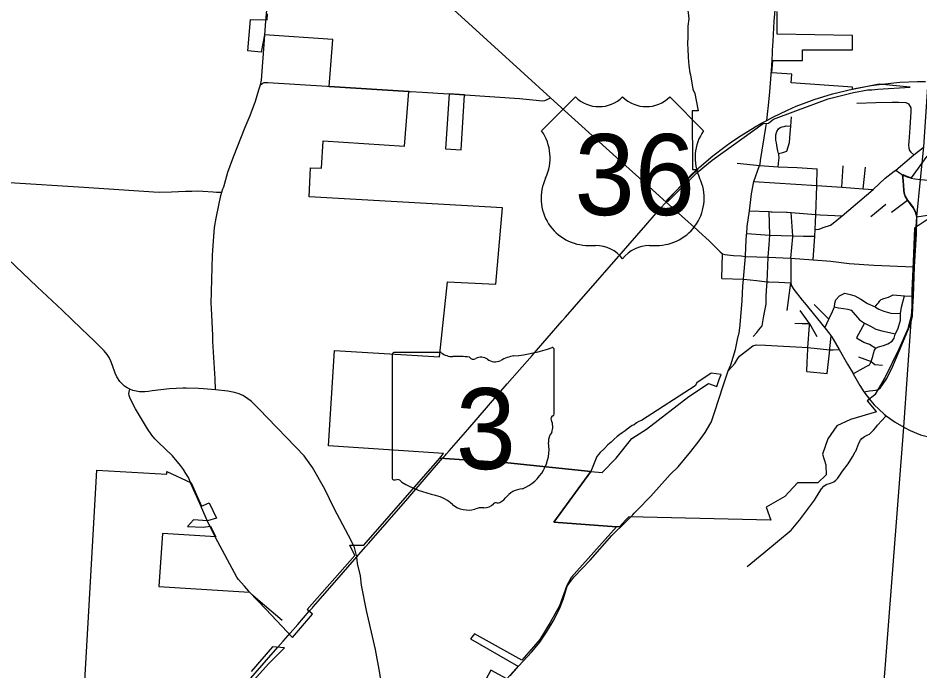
# Model space of a CAD drawing. Extents: x 1729596 to 1925846, y 659247 to 911751.
# Drawn here: x 1855559 to 1871056, y 810051 to 821273 of the extents above; entities that cross this region are included whole.
import ezdxf

# ---------------------------------------------------------------- set-up
doc = ezdxf.new("R2010")
doc.units = 0
for name, color, linetype in [('GM_X_City_Street', 7, 'Continuous'), ('GM_X_Corporation', 7, 'Continuous'), ('GM_X_County_Road', 7, 'Continuous'), ('GM_X_State_Route', 7, 'Continuous'), ('GM_X_State_Shield', 7, 'Continuous'), ('GM_X_Township', 7, 'Continuous'), ('GM_X_Township_Road', 7, 'Continuous'), ('GM_X_US_Route', 7, 'Continuous'), ('GM_X_US_Shield', 7, 'Continuous')]:
    doc.layers.add(name, color=color, linetype=linetype)

msp = doc.modelspace()

# ---------------------------------------------------------------- linework, layer by layer
at = {"layer": 'GM_X_City_Street'}
for points in [[(1859794, 820906), (1859818, 821219)], [(1862296, 820012), (1862506, 819999)], [(1862770, 819982), (1862964, 819970), (1862980, 819969)], [(1863244, 819953), (1864174, 819889), (1864402, 819867), (1864570, 819853), (1864610, 819857), (1864649, 819871), (1864708, 819903)], [(1869969, 819812), (1870296, 819821), (1870580, 819825), (1870662, 819825)], [(1870662, 819825), (1870665, 819825), (1870686, 819825), (1870812, 819821), (1870858, 819797), (1870899, 819732), (1870898, 819669), (1870883, 819386), (1870863, 819146), (1870862, 819092), (1870864, 819034), (1870877, 818999), (1870902, 818968), (1870950, 818924)], [(1868627, 818944), (1868702, 818965), (1868767, 818983), (1868813, 819135), (1868824, 819291), (1868837, 819417), (1868848, 819578)], [(1868318, 818823), (1868408, 819390), (1868417, 819463)], [(1868619, 818717), (1868634, 818829), (1868636, 818865), (1868630, 818931), (1868627, 818944), (1868616, 818991), (1868603, 819050), (1868589, 819130), (1868581, 819174), (1868580, 819266), (1868596, 819326), (1868624, 819370), (1868657, 819390), (1868687, 819404), (1868723, 819412), (1868755, 819418), (1868837, 819417)], [(1870615, 818642), (1870639, 818661), (1870950, 818924), (1871110, 819046)], [(1867916, 818779), (1868190, 818751), (1868191, 818751)], [(1868078, 817555), (1868079, 817572), (1868088, 817688), (1868126, 817958), (1868161, 818253), (1868200, 818465), (1868301, 818741), (1868308, 818760), (1868318, 818823)], [(1868191, 818751), (1868250, 818745), (1868301, 818741), (1868619, 818717), (1868949, 818705), (1869292, 818679)], [(1868836, 817146), (1869223, 817120), (1869252, 817526), (1869257, 817637), (1869326, 817645), (1869394, 817673), (1869522, 817716), (1869565, 817745), (1869717, 817873), (1870254, 818326), (1870457, 818519), (1870615, 818642)], [(1869257, 817637), (1869264, 817763), (1869268, 817897), (1869284, 818388), (1869285, 818397), (1869292, 818679)], [(1869714, 818365), (1869739, 818731)], [(1870083, 818338), (1870123, 818713)], [(1870639, 818661), (1870705, 818615), (1870759, 818578), (1870769, 818573)], [(1868200, 818465), (1869285, 818397), (1869714, 818365), (1870083, 818338), (1870254, 818326)], [(1870569, 817936), (1870841, 818142)], [(1870211, 817860), (1870470, 818075)], [(1868126, 817958), (1868463, 817946), (1868499, 817944), (1868515, 817944)], [(1868465, 817382), (1868477, 817541), (1868463, 817946)], [(1868515, 817944), (1868765, 817935), (1868777, 817934)], [(1868777, 817934), (1868845, 817932), (1869268, 817897), (1869342, 817891), (1869717, 817873)], [(1868870, 817512), (1868872, 817530), (1868845, 817932)], [(1870997, 817576), (1871001, 817788)], [(1868056, 817177), (1868065, 817339), (1868078, 817555)], [(1868079, 817572), (1868477, 817541)], [(1868477, 817541), (1868865, 817530)], [(1868836, 817146), (1868870, 817512)], [(1868865, 817530), (1868872, 817530), (1869053, 817525), (1869252, 817526)], [(1868441, 817012), (1868448, 817163), (1868465, 817382)], [(1867651, 816799), (1867664, 817220)], [(1868026, 816789), (1868056, 817177)], [(1869223, 817120), (1869523, 817094), (1869840, 817054), (1870261, 817024), (1870943, 816996), (1870961, 816995)], [(1868420, 816588), (1868429, 816742), (1868441, 817012)], [(1867651, 816799), (1868026, 816783), (1868029, 816783)], [(1867945, 815848), (1867947, 815858), (1867966, 816000), (1868000, 816416), (1868012, 816665), (1868026, 816783), (1868026, 816789)], [(1868029, 816783), (1868245, 816761), (1868429, 816742), (1868459, 816741)], [(1868459, 816741), (1868634, 816731), (1868837, 816721)], [(1868776, 816244), (1868837, 816721)], [(1868193, 815800), (1868251, 815868), (1868290, 815913), (1868344, 815981), (1868375, 816154), (1868411, 816354), (1868414, 816482), (1868420, 816588)], [(1869420, 815948), (1869492, 816098), (1869556, 816230), (1869590, 816308), (1869593, 816374), (1869609, 816429), (1869672, 816496), (1869765, 816547)], [(1869765, 816547), (1869857, 816521), (1869939, 816498), (1870039, 816440), (1870157, 816365), (1870285, 816308), (1870295, 816304), (1870349, 816267), (1870437, 816233), (1870557, 816202), (1870723, 816195)], [(1869910, 815156), (1870029, 815227), (1870080, 815254), (1870132, 815283), (1870188, 815314), (1870220, 815371), (1870244, 815454), (1870259, 815510), (1870275, 815562), (1870297, 815598), (1870343, 815622), (1870428, 815646), (1870502, 815675), (1870578, 815717), (1870611, 815773), (1870633, 815841), (1870636, 815847), (1870680, 815941), (1870721, 816079), (1870723, 816195), (1870740, 816306), (1870790, 816499)], [(1870285, 816308), (1870321, 816354), (1870345, 816378), (1870368, 816410), (1870392, 816438), (1870436, 816453), (1870516, 816477), (1870596, 816514), (1870790, 816499), (1870933, 816495), (1870947, 816494)], [(1869492, 816098), (1869239, 816348)], [(1869590, 816308), (1869656, 816290), (1869745, 816281), (1869819, 816271), (1869874, 816255), (1870015, 816089), (1870104, 816030), (1870115, 816022), (1870205, 815976), (1870301, 815925), (1870403, 815896), (1870636, 815847)], [(1869157, 816021), (1869157, 816024), (1868996, 816244)], [(1868907, 816028), (1869031, 816023), (1869157, 816024), (1869282, 815797)], [(1869128, 815581), (1869129, 815613), (1869160, 815986), (1869157, 816021)], [(1870104, 816030), (1869966, 815778), (1870093, 815705), (1870133, 815683), (1870187, 815667), (1870297, 815598)], [(1867761, 815208), (1867805, 815310), (1867884, 815579), (1867924, 815749), (1867945, 815848)], [(1869509, 815593), (1869530, 815808)], [(1867761, 815208), (1867878, 815333), (1867925, 815423), (1867955, 815463), (1868186, 815638), (1868244, 815655), (1868405, 815651), (1869129, 815613), (1869506, 815569), (1869567, 815571), (1869669, 815577)], [(1869111, 815196), (1869119, 815352), (1869128, 815581)], [(1869464, 815163), (1869506, 815569), (1869509, 815593)], [(1870002, 815453), (1870220, 815371)], [(1870220, 815371), (1870280, 815316), (1870410, 815305)], [(1867464, 814315), (1867470, 814324), (1867530, 814508), (1867675, 814949), (1867761, 815208)], [(1869111, 815196), (1869464, 815163)], [(1866148, 812764), (1866195, 812814), (1866431, 813056), (1866765, 813427), (1866903, 813557), (1867120, 813823), (1867265, 814005), (1867368, 814147), (1867464, 814315)], [(1858816, 812624), (1858712, 812860)], [(1862504, 807234), (1862441, 807407), (1862377, 807590), (1862238, 807946), (1862134, 808217), (1862091, 808342), (1862056, 808446), (1862054, 808456), (1861975, 808879), (1861910, 809276), (1861885, 809449), (1861803, 809811), (1861778, 810016), (1861699, 810418), (1861546, 811089), (1861463, 811523), (1861444, 811686), (1861392, 811897), (1861379, 812013)]]:
    msp.add_lwpolyline(points, dxfattribs=at)
at = {"layer": 'GM_X_Corporation'}
for points in [[(1867041, 821665), (1867085, 821260), (1867068, 821136), (1867065, 820962), (1867060, 820821), (1867068, 820747), (1867072, 820594), (1867087, 820460), (1867100, 820333), (1867115, 820300), (1867151, 820053), (1867187, 819974), (1867212, 819855), (1867245, 819678), (1867145, 819678), (1867148, 818668), (1867246, 818668), (1867161, 818594), (1866699, 818140), (1866722, 818118), (1867219, 818607), (1867231, 818617), (1867484, 818828), (1868360, 819462), (1868454, 819464), (1868541, 819536), (1868921, 819679), (1869480, 819883), (1869917, 819994), (1870158, 820041), (1870228, 820041), (1870333, 820049), (1870889, 820088), (1870356, 820135), (1869899, 820044), (1869899, 820085), (1868844, 820159), (1868852, 820309), (1868513, 820332), (1868528, 820542), (1869039, 820542), (1869039, 820726), (1869899, 820726), (1869899, 820974), (1868600, 820997), (1868600, 821384)], [(1871257, 817859), (1870965, 817659), (1870940, 817085), (1870914, 816591), (1870918, 816409), (1870920, 816216), (1870850, 815933), (1870694, 815581), (1870461, 815102), (1870281, 814797), (1870152, 814693), (1870300, 814517), (1870310, 814507), (1869865, 814374), (1869626, 814263), (1869472, 814042), (1869383, 813776), (1869438, 813593), (1869447, 813422), (1869302, 813286), (1868954, 813287), (1868735, 813050), (1868415, 812867), (1868495, 812643), (1866054, 812701), (1865997, 812642), (1865896, 812527), (1865843, 812531), (1864768, 812610), (1865403, 813477), (1863975, 813629), (1862805, 813710), (1862871, 813787), (1860894, 813922), (1860996, 815560), (1862803, 815449), (1862941, 816737), (1863769, 816697), (1863883, 818014), (1860562, 818202), (1860587, 818701), (1860771, 818691), (1860802, 819164), (1862199, 819069), (1862276, 820013), (1860906, 820099), (1860970, 820906), (1859791, 820983), (1859738, 820687), (1859505, 820707), (1859552, 821251), (1859841, 821244), (1859848, 821345)], [(1871177, 818898), (1870906, 818525), (1870848, 818543), (1870767, 818577), (1870760, 818526), (1870768, 818476), (1870779, 818314), (1870786, 818263), (1870803, 818212), (1870841, 818142), (1870892, 818081), (1870941, 818016), (1870984, 817932), (1871003, 817857), (1871186, 817888)], [(1856704, 809881), (1856773, 811076), (1856914, 813505), (1858114, 813436), (1858118, 813482), (1858535, 813283), (1858712, 812884), (1858845, 812940), (1858970, 812675), (1858813, 812629), (1858574, 812648), (1858471, 812534), (1858741, 812523), (1858864, 812540), (1858957, 812354), (1858043, 812416), (1857978, 811505), (1859535, 811404), (1859815, 811112), (1860275, 810628), (1860621, 811028), (1860529, 811110), (1861344, 812036), (1861260, 812216), (1861498, 812216), (1862805, 813710), (1863975, 813629), (1865403, 813477), (1864768, 812610), (1865843, 812531), (1865065, 811655), (1864989, 811518), (1864863, 811170), (1864701, 810884), (1864525, 810591), (1864418, 810465), (1864215, 810236), (1863402, 810688), (1863333, 810602), (1864120, 810151), (1864151, 810133), (1864012, 809966)], [(1859404, 809666), (1859863, 810176), (1860139, 810448), (1859933, 810468), (1859566, 810043)], [(1863958, 809914), (1863680, 810064), (1863595, 809906)]]:
    msp.add_lwpolyline(points, dxfattribs=at)
for points in [[(1862906, 819024), (1863171, 819007), (1863230, 819954), (1862964, 819970)], [(1865403, 813477), (1865595, 813463), (1865838, 813709), (1866105, 814049), (1866357, 814208), (1867086, 814766), (1867421, 814993), (1867566, 814942), (1867606, 815063), (1867642, 815146), (1867470, 815167), (1867221, 815005), (1867191, 814953), (1866273, 814357), (1866252, 814350), (1866224, 814337), (1866188, 814318), (1866148, 814284), (1866111, 814270), (1866070, 814243), (1866027, 814208), (1865989, 814179), (1865937, 814144), (1865899, 814117), (1865853, 814081), (1865802, 814037), (1865749, 813986), (1865694, 813935), (1865628, 813870), (1865561, 813807), (1865503, 813738)]]:
    msp.add_lwpolyline(points, close=True, dxfattribs=at)
at = {"layer": 'GM_X_County_Road'}
for points in [[(1855415, 818448), (1856692, 818365), (1857805, 818293), (1857887, 818287), (1857997, 818281), (1858195, 818286), (1858439, 818296), (1858547, 818299), (1858647, 818302), (1858736, 818299), (1858909, 818286), (1858969, 818282), (1859024, 818279), (1859060, 818281), (1859080, 818337), (1859095, 818374), (1859163, 818625), (1859262, 818885), (1859464, 819395), (1859545, 819601), (1859637, 819846), (1859697, 820038), (1859727, 820125), (1859753, 820151), (1859775, 820161), (1859787, 820164), (1859852, 820165), (1860873, 820101)], [(1860873, 820101), (1860906, 820099), (1862276, 820013), (1862296, 820012)], [(1862506, 819999), (1862509, 819999), (1862770, 819982)], [(1862980, 819969), (1863230, 819954), (1863244, 819953)], [(1857182, 815299), (1857153, 815378), (1857124, 815436), (1857089, 815491), (1857039, 815553), (1856865, 815727), (1856650, 815933), (1856316, 816250), (1855886, 816655), (1854135, 818318), (1853948, 818496), (1853892, 818538)], [(1870769, 818573), (1870822, 818549), (1870854, 818540), (1870866, 818536)], [(1870866, 818536), (1870906, 818522), (1870968, 818509), (1871065, 818497), (1871277, 818480)], [(1858745, 814899), (1858660, 814905), (1858449, 814910), (1858391, 814909), (1858164, 814898), (1857861, 814864), (1857798, 814856), (1857739, 814849), (1857648, 814850), (1857559, 814865), (1857530, 814873), (1857479, 814893), (1857433, 814917), (1857388, 814948), (1857347, 814984), (1857307, 815028), (1857257, 815108), (1857229, 815169), (1857182, 815299)], [(1861324, 812212), (1861236, 812378), (1860992, 812846), (1860828, 813174), (1860617, 813548), (1860476, 813746), (1860173, 814063), (1859848, 814400), (1859708, 814543), (1859640, 814615), (1859568, 814682), (1859482, 814748), (1859421, 814784), (1859356, 814815), (1859277, 814840), (1859165, 814861), (1858949, 814884), (1858745, 814899)], [(1866002, 812614), (1866066, 812677), (1866122, 812737), (1866148, 812764)], [(1864113, 810086), (1864158, 810136), (1864387, 810382), (1864526, 810545), (1864640, 810718), (1864769, 810937), (1864875, 811146), (1864930, 811298), (1864995, 811506), (1865050, 811588), (1865117, 811671), (1865392, 811956), (1865763, 812377), (1866002, 812614)], [(1861379, 812013), (1861332, 812198), (1861324, 812212)], [(1863902, 809854), (1863958, 809914), (1864113, 810086)]]:
    msp.add_lwpolyline(points, dxfattribs=at)
at = {"layer": 'GM_X_State_Route'}
for points in [[(1868532, 820875), (1868550, 821219), (1868792, 823921)], [(1868523, 820718), (1868532, 820875)], [(1868515, 820560), (1868520, 820663), (1868523, 820718)], [(1868423, 819513), (1868436, 819621), (1868455, 819771), (1868478, 820007), (1868509, 820452), (1868515, 820560)], [(1866346, 817716), (1866565, 817968), (1866588, 817993)], [(1866588, 817993), (1866693, 818111)], [(1866693, 818111), (1867234, 817626), (1867256, 817606)], [(1864967, 816131), (1865275, 816485), (1865884, 817183), (1866346, 817716)], [(1867256, 817606), (1867435, 817444), (1867478, 817401)], [(1867478, 817401), (1867625, 817254), (1867664, 817220), (1867706, 817207), (1867748, 817201), (1867855, 817194)], [(1867855, 817194), (1867983, 817185), (1868056, 817177)], [(1868056, 817177), (1868448, 817163), (1868836, 817146)], [(1868836, 817146), (1868837, 816776)], [(1868837, 816776), (1868837, 816721), (1868851, 816673), (1868887, 816606), (1869030, 816427), (1869071, 816377)], [(1869071, 816377), (1869420, 815948), (1869509, 815839), (1869530, 815808), (1869534, 815802)], [(1862967, 813834), (1863287, 814202), (1863966, 814984), (1864395, 815476), (1864911, 816067), (1864967, 816131)], [(1869534, 815802), (1869567, 815752), (1869669, 815577), (1869812, 815327), (1869906, 815164)], [(1869906, 815164), (1869910, 815156), (1870025, 814958), (1870094, 814847), (1870207, 814697)], [(1870207, 814697), (1870211, 814693), (1870271, 814626), (1870352, 814549), (1870443, 814463), (1870476, 814436), (1870628, 814325), (1870779, 814239), (1870889, 814182), (1871068, 814112), (1871253, 814061), (1871361, 814039), (1871455, 814026)], [(1862898, 813755), (1862922, 813783), (1862967, 813834)], [(1861588, 812249), (1862256, 813018), (1862855, 813706), (1862898, 813755)], [(1861414, 812052), (1861532, 812184), (1861588, 812249)], [(1860617, 811135), (1860632, 811151), (1860959, 811525), (1861379, 812013), (1861414, 812052)], [(1860234, 810698), (1860366, 810850), (1860563, 811079), (1860617, 811135)], [(1860025, 810459), (1860116, 810563), (1860234, 810698)], [(1853225, 794338), (1854573, 800349), (1855512, 804546), (1855541, 804679), (1855596, 804898), (1855689, 805139), (1855836, 805465), (1855908, 805599), (1856008, 805767), (1856148, 805978), (1856255, 806119), (1856504, 806413), (1857597, 807668), (1858467, 808668), (1858818, 809072), (1859440, 809788), (1860025, 810459)]]:
    msp.add_lwpolyline(points, dxfattribs=at)
at = {"layer": 'GM_X_State_Shield'}
for p, q in [((1861987, 815485), (1861987, 813372)), ((1861987, 815485), (1861987, 813372)), ((1862830, 815522), (1862014, 815522)), ((1862830, 815522), (1862014, 815522)), ((1864771, 814469), (1864771, 815574)), ((1864771, 814469), (1864771, 815574)), ((1864771, 814469), (1864771, 814469)), ((1864771, 814469), (1864771, 814469))]:
    msp.add_line(p, q, dxfattribs=at)
for centre, radius, start, end in [((1862019, 815490), 32.3, 98.1301, 188.1301), ((1862019, 815490), 32.3, 98.1301, 188.1301), ((1863024, 815767), 313, 231.6195, 271.1119), ((1863024, 815767), 313, 231.6195, 271.1119), ((1863779, 818403), 2953, 275.8445, 288.9065), ((1863779, 818403), 2953, 275.8445, 288.9065), ((1864740, 815579), 31, 351.8621, 97.738), ((1864740, 815579), 31, 351.8621, 97.738), ((1863128, 814335), 1123, 80.4867, 94.9883), ((1863128, 814335), 1123, 80.4867, 94.9883), ((1863383, 815501), 90.3, 219.7921, 297.1024), ((1863383, 815501), 90.3, 219.7921, 297.1024), ((1863515, 815257), 188, 54.4667, 119.1411), ((1863515, 815257), 188, 54.4667, 119.1411), ((1863757, 815592), 226, 233.8562, 294.8282), ((1863757, 815592), 226, 233.8562, 294.8282), ((1864156, 814876), 594, 97.3462, 120.7689), ((1864156, 814876), 594, 97.3462, 120.7689), ((1864764, 814388), 48, 107.944, 210.337), ((1864764, 814388), 48, 107.944, 210.337), ((1864738, 814464), 33.2, 289.6038, 7.7341), ((1864738, 814464), 33.2, 289.6038, 7.7341), ((1864459, 814248), 288, 340.033, 23.6496), ((1864459, 814248), 288, 340.033, 23.6496), ((1864882, 814006), 210, 136.8065, 186.9296), ((1864882, 814006), 210, 136.8065, 186.9296), ((1863945, 813865), 739, 292.3089, 8.9858), ((1863945, 813865), 739, 292.3089, 8.9858), ((1862019, 813368), 32.5, 171.9584, 258.3066), ((1862019, 813368), 32.5, 171.9584, 258.3066), ((1862024, 813584), 248, 267.339, 280.6039), ((1862024, 813584), 248, 267.339, 280.6039), ((1862075, 813250), 89.5, 29.7484, 93.2717), ((1862075, 813250), 89.5, 29.7484, 93.2717), ((1863205, 815149), 2132, 240.4129, 257.1985), ((1863205, 815149), 2132, 240.4129, 257.1985), ((1864256, 812779), 404, 94.4031, 142.5768), ((1864256, 812779), 404, 94.4031, 142.5768), ((1862570, 812423), 667, 47.1842, 75.836), ((1862570, 812423), 667, 47.1842, 75.836), ((1863744, 813167), 239, 282.8732, 323.2771), ((1863744, 813167), 239, 282.8732, 323.2771), ((1863291, 813240), 423, 230.7004, 286.2918), ((1863291, 813240), 423, 230.7004, 286.2918), ((1863536, 812509), 348, 85.6951, 111.2099), ((1863536, 812509), 348, 85.6951, 111.2099), ((1863567, 813081), 226, 268.777, 315.5493), ((1863567, 813081), 226, 268.777, 315.5493), ((1863771, 812877), 63.5, 65.7517, 132.6484), ((1863771, 812877), 63.5, 65.7517, 132.6484)]:
    msp.add_arc(centre, radius, start, end, dxfattribs=at)
at = {"layer": 'GM_X_Township'}
msp.add_lwpolyline([(1896867, 801714), (1892288, 802025), (1891297, 802083), (1891221, 802088), (1891165, 802089), (1883392, 802588), (1877369, 802994), (1870008, 803514), (1870309, 808163), (1870779, 814239), (1870903, 816053), (1870933, 816495), (1870943, 816996), (1871003, 817857), (1871065, 818497), (1871124, 819057), (1871199, 820179), (1871965, 831096)], dxfattribs=at)
at = {"layer": 'GM_X_Township_Road'}
for points in [[(1859818, 821219), (1859833, 821406), (1859916, 822663), (1859971, 823438), (1859983, 823596), (1859988, 823723)], [(1859727, 820125), (1859741, 820205), (1859793, 820898), (1859794, 820906)], [(1871001, 817788), (1871003, 817857), (1870979, 817935), (1870937, 818014), (1870874, 818099), (1870841, 818142), (1870803, 818212), (1870786, 818263), (1870779, 818314), (1870768, 818476), (1870760, 818526), (1870759, 818578)], [(1858949, 814884), (1858944, 815073), (1858908, 815711), (1858905, 815815), (1858883, 816289), (1858879, 816365), (1858902, 817190), (1858907, 817282), (1858933, 817671), (1858963, 817835), (1859010, 818058), (1859043, 818222), (1859060, 818281)], [(1870844, 815892), (1870875, 815973), (1870903, 816053), (1870926, 816150), (1870932, 816316), (1870947, 816494), (1870961, 816995), (1870997, 817562), (1870997, 817576)], [(1870094, 814847), (1870189, 814864), (1870245, 814871), (1870293, 814877), (1870336, 814889), (1870372, 814914), (1870477, 815061), (1870573, 815247), (1870701, 815548), (1870821, 815832), (1870844, 815892)], [(1858524, 813285), (1858523, 813288), (1858486, 813376), (1858444, 813445), (1858400, 813513), (1858350, 813585), (1858214, 813747), (1857968, 813983), (1857911, 814041), (1857857, 814102), (1857782, 814210), (1857579, 814557), (1857484, 814732), (1857467, 814783), (1857464, 814822), (1857479, 814893)], [(1868090, 811845), (1868376, 812080), (1868841, 812471), (1868988, 812641), (1869243, 812986), (1869324, 813120), (1869362, 813182), (1869404, 813226), (1869447, 813255), (1869519, 813280), (1869574, 813300), (1869613, 813329), (1869643, 813365), (1869725, 813483), (1869823, 813611), (1869897, 813730), (1869945, 813815), (1869952, 813827), (1870008, 813965), (1870034, 814019), (1870058, 814049), (1870103, 814080), (1870160, 814108), (1870188, 814122), (1870258, 814187), (1870300, 814238), (1870327, 814273), (1870476, 814436)], [(1858712, 812860), (1858703, 812880), (1858602, 813109), (1858524, 813285)], [(1858858, 812530), (1858854, 812539), (1858816, 812624)], [(1858951, 812345), (1858946, 812355), (1858888, 812469), (1858858, 812530)], [(1859516, 811426), (1859452, 811506), (1859339, 811630), (1859319, 811662), (1858951, 812345)], [(1859590, 811355), (1859535, 811404), (1859516, 811426)], [(1860099, 810917), (1859678, 811276), (1859590, 811355)]]:
    msp.add_lwpolyline(points, dxfattribs=at)
at = {"layer": 'GM_X_US_Route'}
for points in [[(1862984, 821471), (1864255, 820317), (1864708, 819903), (1864947, 819685), (1865843, 818874), (1866225, 818531)], [(1869772, 820024), (1869935, 820064), (1870218, 820115), (1870358, 820133), (1870708, 820169), (1871013, 820182), (1871153, 820180)], [(1868423, 819513), (1868530, 819569), (1868780, 819692), (1868932, 819756), (1869103, 819824), (1869240, 819873), (1869556, 819971), (1869772, 820024)], [(1867232, 818676), (1867261, 818703), (1867495, 818904), (1867708, 819068), (1867816, 819145), (1867983, 819256), (1868226, 819404), (1868324, 819459), (1868423, 819513)], [(1867046, 818494), (1867142, 818593), (1867232, 818676)], [(1866225, 818531), (1866693, 818111)], [(1866761, 818189), (1866781, 818212), (1866860, 818300), (1867046, 818494)], [(1866693, 818111), (1866761, 818189)]]:
    msp.add_lwpolyline(points, dxfattribs=at)
at = {"layer": 'GM_X_US_Shield'}
for p, q in [((1865135, 819917), (1864555, 819337)), ((1865135, 819917), (1864555, 819337)), ((1867339, 819337), (1866759, 819917)), ((1867339, 819337), (1866759, 819917)), ((1865367, 817365), (1865483, 817365)), ((1865367, 817365), (1865483, 817365)), ((1866411, 817365), (1866527, 817365)), ((1866411, 817365), (1866527, 817365))]:
    msp.add_line(p, q, dxfattribs=at)
for centre, radius, start, end in [((1865541, 820331), 580, 225.573, 314.427), ((1865541, 820331), 580, 225.573, 314.427), ((1866353, 820331), 580, 225.573, 314.427), ((1866353, 820331), 580, 225.573, 314.427), ((1863890, 818871), 812, 334.5471, 35.0009), ((1863890, 818871), 812, 334.5471, 35.0009), ((1868004, 818871), 812, 144.9991, 205.4529), ((1868004, 818871), 812, 144.9991, 205.4529), ((1865358, 818177), 812, 154.8319, 270.6383), ((1865358, 818177), 812, 154.8319, 270.6383), ((1866536, 818177), 812, 269.3617, 25.1681), ((1866536, 818177), 812, 269.3617, 25.1681), ((1865483, 816784), 580, 36.8699, 90), ((1865483, 816784), 580, 36.8699, 90), ((1866411, 816784), 580, 90, 143.1301), ((1866411, 816784), 580, 90, 143.1301)]:
    msp.add_arc(centre, radius, start, end, dxfattribs=at)

# ---------------------------------------------------------------- texts
at = {"layer": 'GM_X_State_Shield'}
msp.add_text('3', height=1392, dxfattribs=at).set_placement((1863079, 813521))
msp.add_text('3', height=1392, dxfattribs=at).set_placement((1863079, 813521))
at = {"layer": 'GM_X_US_Shield'}
msp.add_text('36', height=1392.2, dxfattribs=at).set_placement((1865120, 817887))
msp.add_text('36', height=1392.2, dxfattribs=at).set_placement((1865120, 817887))

doc.saveas('drawing.dxf')
